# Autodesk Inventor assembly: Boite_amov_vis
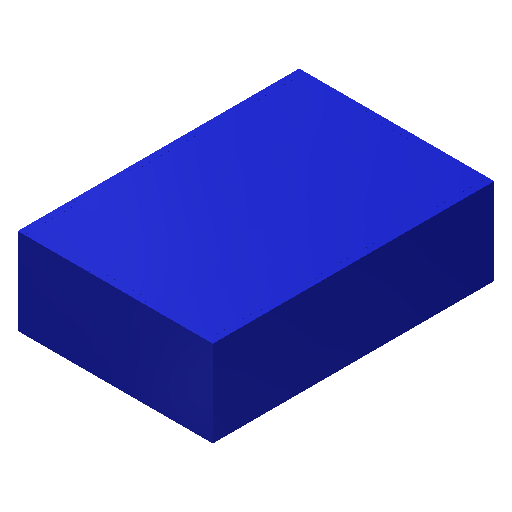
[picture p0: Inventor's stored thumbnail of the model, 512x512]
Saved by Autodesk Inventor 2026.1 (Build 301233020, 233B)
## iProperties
Part Number: Boite_amov_vis
Material: Générique
Document SubType Name: Assembly
Designer: ficho
Author: ficho
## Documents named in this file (4)
- M:\STI2D\IT\Escape game\Escape-game\Boite\boite_amovible.iam
- M:\STI2D\IT\Escape game\Escape-game\Boite\boite_amovible_face.ipt
- M:\STI2D\IT\Escape game\Escape-game\Boite\boite_amovible_cote.ipt
- M:\STI2D\IT\Escape game\Escape-game\Boite\boite_amovible_dessus.ipt
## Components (6 placed, 3 different names)
1. boite_amovible_face:1 — Affleurement:1, Affleurement:2, Placage:1, Affleurement:4, Affleurement:5, Affleurement:6, Placage:2
2. boite_amovible_face:2 — Affleurement:1, Affleurement:2, Placage:1, Affleurement:3, Affleurement:7, Affleurement:9
3. boite_amovible_cote:1 — Affleurement:3, Affleurement:8
4. boite_amovible_cote:2 — Affleurement:4, Affleurement:5, Affleurement:6
5. boite_amovible_dessus:1 — Affleurement:7
6. boite_amovible_dessus:2 — Placage:2, Affleurement:8, Affleurement:9
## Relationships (11: Flush 9, Mate 2)
- Affleurement:1 [Flush]: boite_amovible_face:1 ↔ boite_amovible_face:2
- Affleurement:2 [Flush]: boite_amovible_face:1 ↔ boite_amovible_face:2
- Placage:1 [Mate]: boite_amovible_face:1 ↔ boite_amovible_face:2
- Affleurement:3 [Flush]: boite_amovible_face:2 ↔ boite_amovible_cote:1
- Affleurement:4 [Flush]: boite_amovible_face:1 ↔ boite_amovible_cote:2
- Affleurement:5 [Flush]: boite_amovible_face:1 ↔ boite_amovible_cote:2
- Affleurement:6 [Flush]: boite_amovible_face:1 ↔ boite_amovible_cote:2
- Affleurement:7 [Flush]: boite_amovible_face:2 ↔ boite_amovible_dessus:1
- Placage:2 [Mate]: boite_amovible_face:1 ↔ boite_amovible_dessus:2
- Affleurement:8 [Flush]: boite_amovible_cote:1 ↔ boite_amovible_dessus:2
- Affleurement:9 [Flush]: boite_amovible_face:2 ↔ boite_amovible_dessus:2
